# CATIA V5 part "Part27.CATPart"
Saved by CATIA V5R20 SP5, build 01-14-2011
Part number: Part27
Material "Water": density 1000 kg/m3
Bounding box of the stored display mesh (mm): x -1.919 to 1.919, y -2 to 2, z -1.919 to 1.919
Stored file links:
  D:\新建文件夹\Part27.CATPart
  C:\Program Files\Dassault Systemes\B20\intel_a\startup\materials\Catalog.CATMaterial
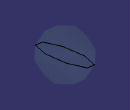
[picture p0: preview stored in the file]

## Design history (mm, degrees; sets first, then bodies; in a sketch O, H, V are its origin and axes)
Body1 (main body), material "Water"
  Sketch1 on xy-plane, origin (0, 0, 0), H (1, 0, 0), V (0, 1, 0)
    arc A1 centre (0, 0) radius 2 from (0, -2) to (0, 2) ccw
    axis line L1 (0, 2.6954) -> (0, -2.923)
    point P1 (0, 2.6954)
    point P3 (0, 2)
    point P4 (0, -2)
    radius A1 = 2
    coincidence: P1 V, L1 P3, L1 P4
    vertical: L1 V
  Shaft1: profile Sketch1, axis Sketch1.L1, angle 360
